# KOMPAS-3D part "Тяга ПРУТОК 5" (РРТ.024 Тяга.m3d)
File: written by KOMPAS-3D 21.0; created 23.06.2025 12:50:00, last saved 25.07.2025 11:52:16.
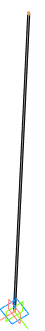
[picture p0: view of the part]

Document properties: Полное имя файла: C:\Users\User\Desktop\Ручной ротатор КД\Модели КД\РРТ.024 Тяга.m3d; Автор: User

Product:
- Part/product: Тяга ПРУТОК 5
    Масса: 0.234849
    Форматы листов документа: A4

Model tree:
1. Эскиз:1
2. Элемент выдавливания:1
     Расстояние 1 = 1522.5
3. Условное изображение резьбы:1  (with: Элемент выдавливания:1)  (labels: M5; cil0_24705-2004 coarse)
     Длина резьбы = 10; Шаг резьбы = 0.8; Номинальный диаметр резьбы = 5
4. Подгонка:1  (with: Элемент выдавливания:1)
5. Условное изображение резьбы:2  (with: Элемент выдавливания:1)  (labels: M5; cil0_24705-2004 coarse)
     Длина резьбы = 10; Шаг резьбы = 0.8; Номинальный диаметр резьбы = 5
6. Подгонка:2  (with: Элемент выдавливания:1)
